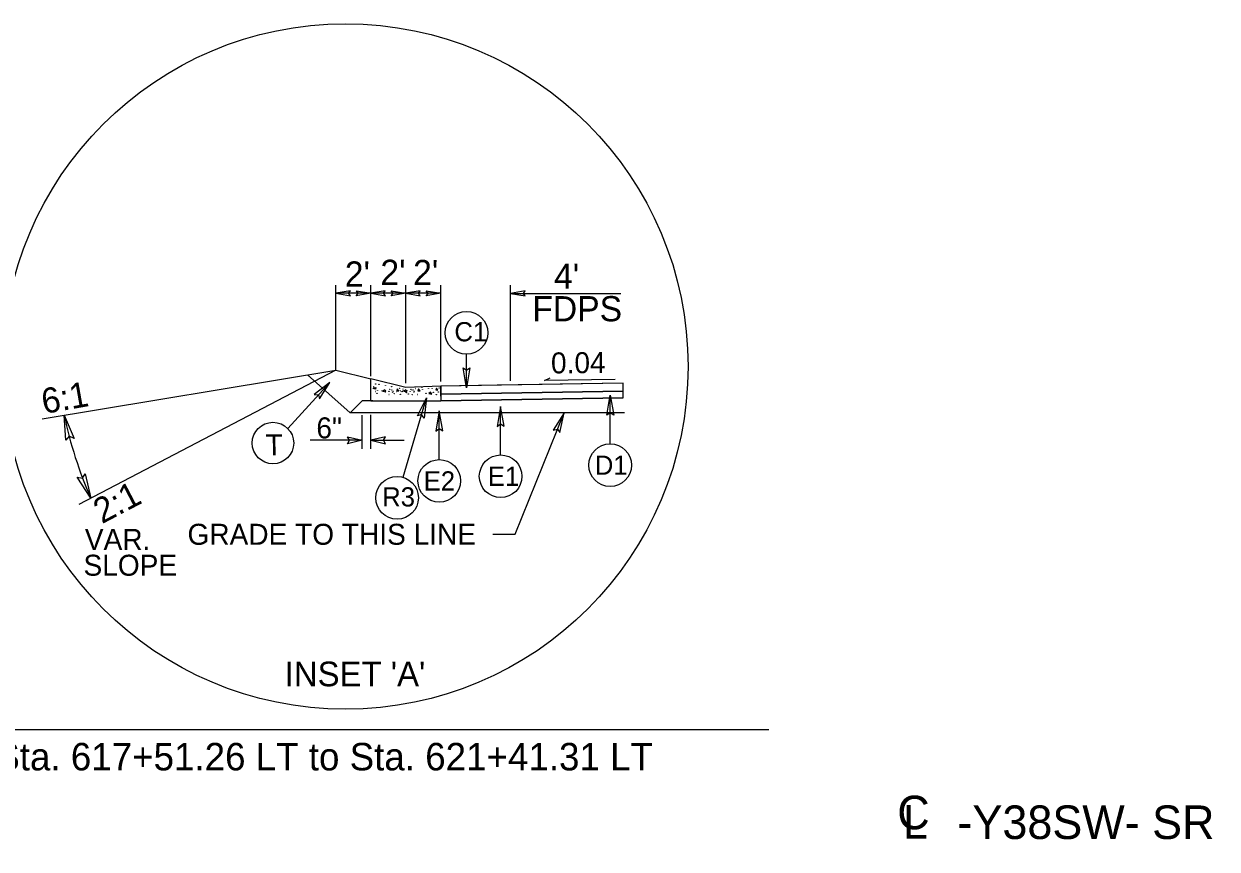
# Model space of a CAD drawing. Extents: x 2294455 to 2294795, y 719276 to 719941.
# Drawn here: x 2294501.1 to 2294590, y 719561.1 to 719622.6 of the extents above; entities that cross this region are included whole.
import ezdxf

# ---------------------------------------------------------------- set-up
doc = ezdxf.new("R2010")
doc.units = 0
for name, color, linetype in [('Default', 7, 'Continuous'), ('Old_Level_1', 7, 'Continuous'), ('Old_Level_11', 7, 'Continuous'), ('Old_Level_2', 7, 'Continuous'), ('Old_Level_3', 7, 'Continuous'), ('Prop Dimension Text', 7, 'Continuous'), ('Typical Curb CELL', 7, 'Continuous'), ('Typical Hinge Slope Arterial CELL', 7, 'Continuous'), ('Typical ID Circle CELL', 7, 'Continuous'), ('Typical Terminator CELL', 7, 'Continuous'), ('Typical Text ID Circle CELL', 7, 'Continuous')]:
    doc.layers.add(name, color=color, linetype=linetype)

# ---------------------------------------------------------------- blocks, each defined once
blk = doc.blocks.new('TERMINATOR')
at = {"layer": 'Default'}
blk.add_lwpolyline([(-0.357, 0.062), (0, 0), (-0.359, -0.063), (-0.313, 0)], close=True, dxfattribs=at)

msp = doc.modelspace()

# ---------------------------------------------------------------- linework, layer by layer
at = {"layer": 'Default'}
for p, q in [((2294534.079, 719595.472), (2294534.079, 719597.982)), ((2294532.155, 719595.6), (2294532.155, 719595.6)), ((2294544.775, 719591.305), (2294544.775, 719594.926)), ((2294536.618, 719590.476), (2294536.618, 719594.097)), ((2294526.305, 719590.939), (2294526.305, 719593.428)), ((2294526.955, 719590.939), (2294526.955, 719593.464)), ((2294532.05, 719590.134), (2294532.05, 719593.754)), ((2294537.7, 719584.573), (2294541.336, 719593.615)), ((2294526.305, 719591.569), (2294522.43, 719591.569)), ((2294526.955, 719591.569), (2294529.438, 719591.569)), ((2294536.028, 719584.572), (2294537.7, 719584.573))]:
    msp.add_line(p, q, dxfattribs=at)
for points in [[(2294534.335, 719596.961), (2294534.079, 719595.472), (2294533.815, 719596.969), (2294534.079, 719596.779)], [(2294544.519, 719593.438), (2294544.775, 719594.926), (2294545.04, 719593.429), (2294544.775, 719593.62)], [(2294530.427, 719593.38), (2294531.102, 719594.73), (2294530.923, 719593.221), (2294530.724, 719593.48)], [(2294536.874, 719592.609), (2294536.618, 719594.097), (2294536.353, 719592.6), (2294536.618, 719592.791)], [(2294532.306, 719592.266), (2294532.05, 719593.754), (2294531.785, 719592.258), (2294532.05, 719592.448)], [(2294541.018, 719592.138), (2294541.336, 719593.615), (2294540.532, 719592.325), (2294540.848, 719592.403)]]:
    msp.add_lwpolyline(points, close=True, dxfattribs=at)
for points in [[(2294545.745, 719595.225), (2294545.745, 719595.225), (2294545.745, 719595.82), (2294532.155, 719595.6)], [(2294532.155, 719595.6), (2294532.155, 719595.6), (2294532.155, 719595.004)], [(2294532.155, 719595.004), (2294545.745, 719595.225)]]:
    msp.add_lwpolyline(points, dxfattribs=at)
for centre in [(2294534.079, 719599.57), (2294536.618, 719588.888), (2294544.775, 719589.717), (2294532.05, 719588.546), (2294528.906, 719587.286)]:
    msp.add_circle(centre, 1.588, dxfattribs=at)
at = {"layer": 'Old_Level_1'}
for p, q in [((2294524.355, 719596.789), (2294526.955, 719596.141)), ((2294545.745, 719595.82), (2294536.368, 719595.668)), ((2294539.886, 719596.016), (2294540.303, 719596.222)), ((2294545.141, 719596.101), (2294539.886, 719596.016)), ((2294536.368, 719595.668), (2294532.155, 719595.6)), ((2294545.745, 719595.225), (2294532.155, 719595.004)), ((2294545.745, 719595.225), (2294532.155, 719595.004)), ((2294532.155, 719595.004), (2294532.155, 719594.508)), ((2294545.745, 719594.728), (2294545.745, 719595.225)), ((2294527.091, 719594.508), (2294526.305, 719594.508)), ((2294545.745, 719594.728), (2294532.155, 719594.508)), ((2294532.155, 719594.508), (2294545.745, 719594.728)), ((2294545.745, 719594.728), (2294545.745, 719594.728)), ((2294545.83, 719593.615), (2294525.411, 719593.615))]:
    msp.add_line(p, q, dxfattribs=at)
msp.add_lwpolyline([(2294525.411, 719593.615), (2294526.305, 719594.508)], dxfattribs=at)
at = {"layer": 'Old_Level_11'}
for p, q in [((2294524.355, 719596.789), (2294524.355, 719603.124)), ((2294526.955, 719596.339), (2294526.955, 719603.124)), ((2294529.555, 719595.812), (2294529.555, 719603.124)), ((2294532.155, 719595.952), (2294532.155, 719603.124)), ((2294537.363, 719596.008), (2294537.363, 719603.124)), ((2294532.155, 719602.511), (2294524.355, 719602.511)), ((2294537.363, 719602.51), (2294545.564, 719602.51)), ((2294495.056, 719570.029), (2294556.581, 719570.029))]:
    msp.add_line(p, q, dxfattribs=at)
for points in [[(2294525.431, 719602.696), (2294524.355, 719602.511), (2294525.437, 719602.32), (2294525.299, 719602.511)], [(2294525.878, 719602.696), (2294526.955, 719602.511), (2294525.872, 719602.319), (2294526.01, 719602.511)], [(2294528.031, 719602.696), (2294526.955, 719602.511), (2294528.037, 719602.319), (2294527.899, 719602.511)], [(2294528.478, 719602.696), (2294529.555, 719602.511), (2294528.472, 719602.319), (2294528.61, 719602.511)], [(2294530.631, 719602.696), (2294529.555, 719602.511), (2294530.637, 719602.319), (2294530.499, 719602.511)], [(2294531.078, 719602.696), (2294532.155, 719602.511), (2294531.072, 719602.319), (2294531.21, 719602.51)], [(2294538.439, 719602.696), (2294537.363, 719602.51), (2294538.445, 719602.319), (2294538.308, 719602.51)], [(2294504.246, 719591.573), (2294504.131, 719593.438), (2294504.876, 719591.712), (2294504.503, 719591.865)], [(2294505.686, 719589.072), (2294506.117, 719587.255), (2294505.09, 719588.829), (2294505.483, 719588.741)]]:
    msp.add_lwpolyline(points, close=True, dxfattribs=at)
msp.add_circle((2294525.061, 719597.061), 25.511, dxfattribs=at)
at = {"layer": 'Typical Curb CELL'}
for p, q in [((2294526.955, 719594.508), (2294526.955, 719596.141)), ((2294529.555, 719595.491), (2294526.955, 719596.141)), ((2294527.137, 719595.437), (2294527.332, 719595.494)), ((2294527.311, 719595.379), (2294527.137, 719595.437)), ((2294527.332, 719595.494), (2294527.311, 719595.379)), ((2294527.985, 719595.332), (2294527.854, 719595.237)), ((2294527.854, 719595.237), (2294528.064, 719595.187)), ((2294528.064, 719595.187), (2294527.985, 719595.332)), ((2294528.924, 719595.403), (2294528.88, 719595.259)), ((2294528.88, 719595.259), (2294529.032, 719595.251)), ((2294529.032, 719595.251), (2294528.924, 719595.403)), ((2294529.566, 719595.332), (2294529.435, 719595.237)), ((2294529.435, 719595.237), (2294529.645, 719595.187)), ((2294532.155, 719595.6), (2294529.555, 719595.491)), ((2294529.645, 719595.187), (2294529.566, 719595.332)), ((2294530.505, 719595.403), (2294530.461, 719595.259)), ((2294530.461, 719595.259), (2294530.614, 719595.251)), ((2294530.614, 719595.251), (2294530.505, 719595.403)), ((2294531.407, 719595.15), (2294531.276, 719595.055)), ((2294531.276, 719595.055), (2294531.486, 719595.005)), ((2294531.486, 719595.005), (2294531.407, 719595.15)), ((2294531.831, 719595.458), (2294531.787, 719595.315)), ((2294531.787, 719595.315), (2294531.94, 719595.307)), ((2294531.94, 719595.307), (2294531.831, 719595.458)), ((2294532.155, 719594.861), (2294532.155, 719595.6)), ((2294526.955, 719594.508), (2294532.155, 719594.508))]:
    msp.add_line(p, q, dxfattribs=at)
for centre in [(2294527.173, 719595.546), (2294527.296, 719595.2), (2294527.313, 719595.759), (2294527.412, 719595.065), (2294527.448, 719595.264), (2294527.565, 719595.729), (2294527.773, 719595.3), (2294527.794, 719595.236), (2294528.018, 719595.128), (2294528.044, 719595.636), (2294528.054, 719595.256), (2294528.296, 719594.979), (2294528.3, 719595.207), (2294528.36, 719595.353), (2294528.498, 719595.557), (2294528.519, 719595.317), (2294528.561, 719595.157), (2294528.631, 719595.2), (2294528.695, 719595.034), (2294528.877, 719595.2), (2294529.029, 719595.264), (2294529.075, 719595.446), (2294529.148, 719595.252), (2294529.155, 719594.998), (2294529.269, 719595.194), (2294529.341, 719595.375), (2294529.354, 719595.3), (2294529.376, 719595.236), (2294529.591, 719595.108), (2294529.636, 719595.256), (2294529.738, 719595.01), (2294529.882, 719595.207), (2294529.941, 719595.353), (2294530.005, 719595.314), (2294530.033, 719594.961), (2294530.1, 719595.317), (2294530.142, 719595.157), (2294530.213, 719595.2), (2294530.288, 719595.425), (2294530.432, 719594.979), (2294530.753, 719595.52), (2294530.801, 719595.361), (2294531.058, 719595.071), (2294531.248, 719595.421), (2294531.518, 719595.434), (2294531.611, 719595.139), (2294531.831, 719594.967), (2294531.979, 719595.17), (2294532.028, 719595.471)]:
    msp.add_circle(centre, 0.0102, dxfattribs=at)
at = {"layer": 'Typical Hinge Slope Arterial CELL'}
for p, q in [((2294502.475, 719593.164), (2294524.355, 719596.789)), ((2294524.355, 719596.789), (2294505.22, 719586.786)), ((2294522.241, 719596.438), (2294525.411, 719593.615))]:
    msp.add_line(p, q, dxfattribs=at)
msp.add_arc((2294532.504, 719599.155), 28.944, 191.39052, 204.27438, dxfattribs=at)
at = {"layer": 'Typical ID Circle CELL'}
for p, q in [((2294520.783, 719592.44), (2294523.9, 719595.872)), ((2294529.352, 719588.813), (2294531.102, 719594.73))]:
    msp.add_line(p, q, dxfattribs=at)
msp.add_circle((2294519.668, 719591.364), 1.545, dxfattribs=at)
at = {"layer": 'Typical Terminator CELL'}
msp.add_lwpolyline([(2294523.12, 719594.647), (2294523.9, 719595.872), (2294522.744, 719594.978), (2294523.056, 719594.942)], close=True, dxfattribs=at)

# ---------------------------------------------------------------- block references
at = {"layer": 'Default', "xscale": 3.0310846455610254}
for p, yscale, rotation in [((2294526.305, 719591.569), 4.350552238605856, -5.199035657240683e-05), ((2294526.955, 719591.569), -4.350552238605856, -179.99994800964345)]:
    msp.add_blockref('TERMINATOR', p, dxfattribs=dict(at, yscale=yscale, rotation=rotation))

# ---------------------------------------------------------------- texts
at = {"layer": 'Default'}
for s, p in [('C1', (2294533.172, 719598.938)), ('E1', (2294535.661, 719588.174)), ('D1', (2294543.625, 719589.003)), ('E2', (2294530.888, 719587.831)), ('R3', (2294527.798, 719586.642))]:
    msp.add_text(s, height=1.4292, rotation=359.99995, dxfattribs=at).set_placement(p)
at = {"layer": 'Old_Level_1'}
for s, height, rotation, p in [('0.04', 1.5625, 0.47187, (2294540.372, 719596.545)), ("INSET 'A'", 1.8334, 359.99996, (2294520.537, 719573.257)), ('-L- Sta. 617+51.26 LT to Sta. 621+41.31 LT', 2.04545, 0, (2294494.888, 719566.994))]:
    msp.add_text(s, height=height, rotation=rotation, dxfattribs=at).set_placement(p)
at = {"layer": 'Old_Level_11'}
for s, height, rotation, p in [("2'", 1.875, 359.99996, (2294525.016, 719603.01)), ("2'", 1.875, 359.99996, (2294527.666, 719603.135)), ("2'", 1.875, 359.99996, (2294530.102, 719603.124)), ("4'", 1.875, 359.99996, (2294540.592, 719602.854)), ('FDPS', 1.875, 359.99996, (2294538.974, 719600.427)), ('6:1', 1.875, 10.05046, (2294502.611, 719593.521)), ('2:1', 1.875, 27.64585, (2294506.932, 719585.32)), ('GRADE TO THIS LINE', 1.5625, 0.00004, (2294513.303, 719583.79))]:
    msp.add_text(s, height=height, rotation=rotation, dxfattribs=at).set_placement(p)
at = {"layer": 'Old_Level_2'}
for s, rotation, p in [('C', 0.00004, (2294566.145, 719562.609)), ('L', 0.05314, (2294566.565, 719561.908))]:
    msp.add_text(s, height=2.5, rotation=rotation, dxfattribs=at).set_placement(p)
at = {"layer": 'Old_Level_3'}
msp.add_text('-Y38SW- SR 1809 (PINE MOUNTAIN RD)', height=2.5, rotation=360, dxfattribs=at).set_placement((2294570.631, 719561.884))
at = {"layer": 'Prop Dimension Text'}
msp.add_text('6"', height=1.5625, dxfattribs=at).set_placement((2294522.899, 719591.713))
at = {"layer": 'Typical Hinge Slope Arterial CELL'}
for s, p in [('VAR. ', (2294505.661, 719583.409)), ('SLOPE', (2294505.56, 719581.486))]:
    msp.add_text(s, height=1.5625, dxfattribs=at).set_placement(p)
at = {"layer": 'Typical Text ID Circle CELL'}
msp.add_text('T', height=1.562, rotation=1.02715, dxfattribs=at).set_placement((2294519.132, 719590.44))

doc.saveas('drawing.dxf')
